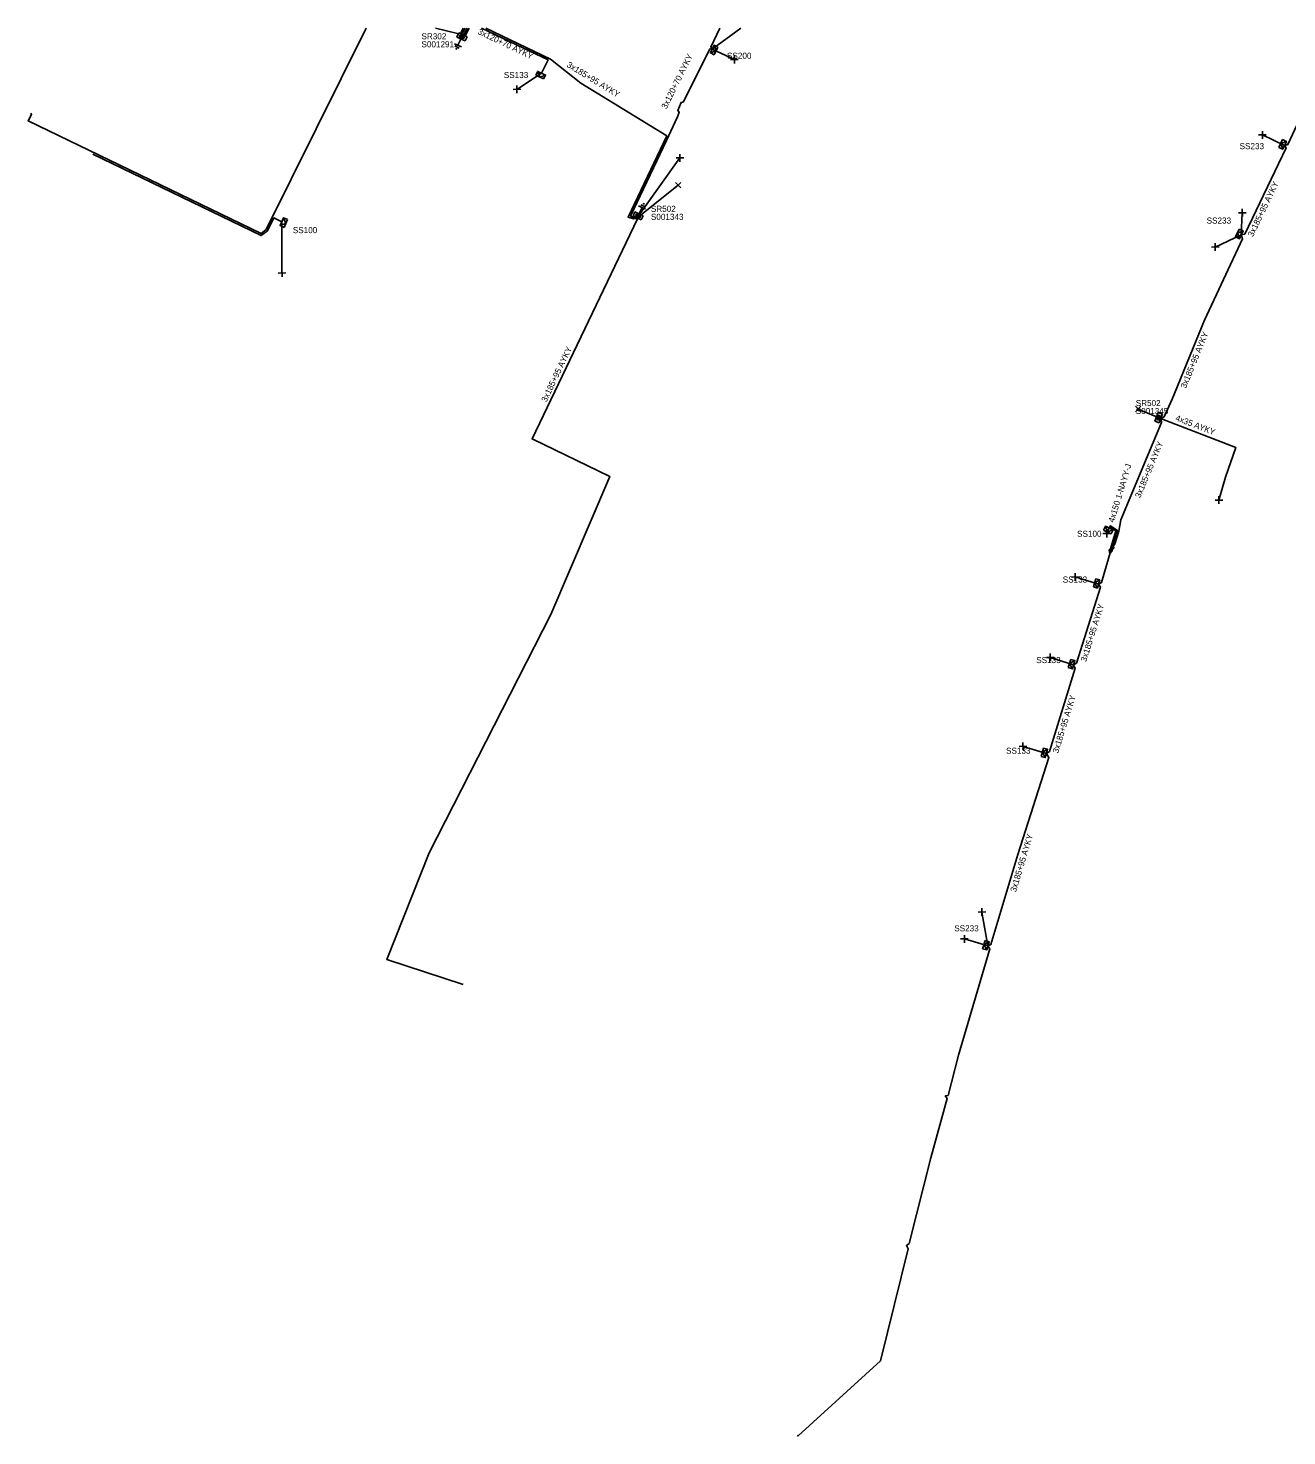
# Model space of a CAD drawing. Extents: x -762284 to -761419, y -1155250 to -1154991.
# Drawn here: x -762284.5 to -762078.9, y -1155230 to -1155000 of the extents above; entities that cross this region are included whole.
import ezdxf

# ---------------------------------------------------------------- set-up
doc = ezdxf.new("R2010")
doc.units = 0
for name, color, linetype in [('Vrstva 15', 7, 'Continuous'), ('Vrstva 19', 7, 'Continuous'), ('Vrstva 28', 7, 'Continuous'), ('Vrstva 29', 7, 'Continuous'), ('Vrstva 30', 7, 'Continuous'), ('Vrstva 31', 7, 'Continuous'), ('Vrstva 33', 7, 'Continuous'), ('Vrstva 34', 7, 'Continuous'), ('Vrstva 5', 7, 'Continuous'), ('Vrstva 59', 7, 'Continuous'), ('Vrstva 6', 7, 'Continuous')]:
    doc.layers.add(name, color=color, linetype=linetype)

msp = doc.modelspace()

# ---------------------------------------------------------------- linework, layer by layer
at = {"layer": 'Vrstva 15'}
for points in [[(-762213.688, -1155003.069), (-762214.821, -1155002.541)], [(-762214.038, -1155003.248), (-762214.751, -1155002.915)], [(-762214.519, -1155003.371), (-762214.635, -1155003.317)], [(-762214.398, -1155003.428), (-762214.519, -1155003.371)], [(-762213.726, -1155001.672), (-762214.254, -1155002.805)], [(-762184.412, -1155028.842), (-762183.698, -1155029.175)], [(-762184.052, -1155028.663), (-762183.931, -1155028.719)], [(-762183.931, -1155028.719), (-762183.815, -1155028.773)], [(-762184.762, -1155029.021), (-762183.629, -1155029.55)], [(-762184.724, -1155030.418), (-762184.195, -1155029.286)]]:
    msp.add_lwpolyline(points, dxfattribs=at)
at = {"layer": 'Vrstva 19'}
for points in [[(-762107.407, -1155085.384), (-762107.521, -1155084.836), (-762107.89, -1155085.255), (-762107.78, -1155085.802), (-762107.407, -1155085.384)], [(-762107.551, -1155084.963), (-762107.83, -1155085.271), (-762107.745, -1155085.669), (-762107.468, -1155085.368), (-762107.551, -1155084.963)], [(-762107.584, -1155085.084), (-762107.769, -1155085.287), (-762107.712, -1155085.563), (-762107.529, -1155085.352), (-762107.584, -1155085.084)], [(-762107.615, -1155085.202), (-762107.708, -1155085.304), (-762107.681, -1155085.446), (-762107.59, -1155085.335), (-762107.615, -1155085.202)], [(-762107.15, -1155084.903), (-762107.245, -1155084.352), (-762107.629, -1155084.757), (-762107.538, -1155085.308), (-762107.15, -1155084.903)], [(-762107.279, -1155084.477), (-762107.568, -1155084.776), (-762107.497, -1155085.176), (-762107.211, -1155084.885), (-762107.279, -1155084.477)], [(-762107.316, -1155084.597), (-762107.508, -1155084.794), (-762107.461, -1155085.072), (-762107.271, -1155084.867), (-762107.316, -1155084.597)], [(-762107.352, -1155084.714), (-762107.448, -1155084.812), (-762107.426, -1155084.955), (-762107.331, -1155084.848), (-762107.352, -1155084.714)]]:
    msp.add_lwpolyline(points, dxfattribs=at)
at = {"layer": 'Vrstva 28'}
for points in [[(-762214.136, -1155000.771), (-762214.453, -1155001.45)], [(-762212.777, -1155001.404), (-762214.136, -1155000.771)], [(-762213.876, -1155001.094), (-762214.036, -1155001.436)], [(-762213.853, -1155001.157), (-762213.973, -1155001.413)], [(-762213.831, -1155001.219), (-762213.91, -1155001.391)], [(-762213.202, -1155001.408), (-762213.876, -1155001.094)], [(-762213.265, -1155001.431), (-762213.853, -1155001.157)], [(-762213.808, -1155001.282), (-762213.848, -1155001.368)], [(-762213.327, -1155001.454), (-762213.831, -1155001.219)], [(-762213.39, -1155001.477), (-762213.808, -1155001.282)], [(-762214.453, -1155001.45), (-762213.094, -1155002.084)], [(-762214.036, -1155001.436), (-762213.362, -1155001.751)], [(-762213.973, -1155001.413), (-762213.384, -1155001.688)], [(-762213.91, -1155001.391), (-762213.407, -1155001.625)], [(-762213.848, -1155001.368), (-762213.43, -1155001.562)], [(-762213.79, -1155001.342), (-762213.448, -1155001.502)], [(-762213.43, -1155001.562), (-762213.39, -1155001.477)], [(-762213.407, -1155001.625), (-762213.327, -1155001.454)], [(-762213.384, -1155001.688), (-762213.265, -1155001.431)], [(-762213.362, -1155001.751), (-762213.202, -1155001.408)], [(-762213.094, -1155002.084), (-762212.777, -1155001.404)], [(-762185.356, -1155030.005), (-762185.673, -1155030.685)], [(-762185.673, -1155030.685), (-762184.314, -1155031.319)], [(-762183.997, -1155030.639), (-762185.356, -1155030.005)], [(-762185.088, -1155030.339), (-762185.248, -1155030.681)], [(-762185.248, -1155030.681), (-762184.574, -1155030.996)], [(-762185.065, -1155030.401), (-762185.185, -1155030.658)], [(-762185.185, -1155030.658), (-762184.596, -1155030.933)], [(-762185.043, -1155030.464), (-762185.122, -1155030.636)], [(-762185.122, -1155030.636), (-762184.619, -1155030.87)], [(-762184.414, -1155030.653), (-762185.088, -1155030.339)], [(-762184.477, -1155030.676), (-762185.065, -1155030.401)], [(-762185.02, -1155030.527), (-762185.06, -1155030.613)], [(-762185.06, -1155030.613), (-762184.642, -1155030.807)], [(-762184.539, -1155030.699), (-762185.043, -1155030.464)], [(-762184.602, -1155030.722), (-762185.02, -1155030.527)], [(-762184.66, -1155030.747), (-762185.002, -1155030.587)], [(-762184.642, -1155030.807), (-762184.602, -1155030.722)], [(-762184.619, -1155030.87), (-762184.539, -1155030.699)], [(-762184.596, -1155030.933), (-762184.477, -1155030.676)], [(-762184.574, -1155030.996), (-762184.414, -1155030.653)], [(-762184.314, -1155031.319), (-762183.997, -1155030.639)], [(-762099.902, -1155062.807), (-762100.464, -1155064.198)], [(-762099.866, -1155063.223), (-762100.145, -1155063.913)], [(-762099.84, -1155063.285), (-762100.084, -1155063.887)], [(-762099.814, -1155063.346), (-762100.022, -1155063.861)], [(-762099.788, -1155063.408), (-762099.961, -1155063.835)], [(-762099.207, -1155063.088), (-762099.902, -1155062.807)], [(-762099.516, -1155063.365), (-762099.866, -1155063.223)], [(-762099.847, -1155063.932), (-762099.639, -1155063.417)], [(-762099.577, -1155063.391), (-762099.84, -1155063.285)], [(-762099.821, -1155063.993), (-762099.577, -1155063.391)], [(-762099.639, -1155063.417), (-762099.814, -1155063.346)], [(-762099.795, -1155064.055), (-762099.516, -1155063.365)], [(-762099.7, -1155063.443), (-762099.788, -1155063.408)], [(-762099.769, -1155064.479), (-762099.207, -1155063.088)], [(-762100.464, -1155064.198), (-762099.769, -1155064.479)], [(-762100.145, -1155063.913), (-762099.795, -1155064.055)], [(-762100.084, -1155063.887), (-762099.821, -1155063.993)], [(-762100.022, -1155063.861), (-762099.847, -1155063.932)], [(-762099.961, -1155063.835), (-762099.873, -1155063.87)], [(-762099.76, -1155063.464), (-762099.901, -1155063.814)], [(-762099.873, -1155063.87), (-762099.7, -1155063.443)]]:
    msp.add_lwpolyline(points, dxfattribs=at)
at = {"layer": 'Vrstva 31'}
for points in [[(-762172.392, -1155004.353), (-762173.027, -1155004.058), (-762172.435, -1155002.789), (-762171.801, -1155003.085)], [(-762172.096, -1155003.719), (-762172.435, -1155002.789)], [(-762172.392, -1155004.353), (-762171.801, -1155003.085)], [(-762172.096, -1155003.719), (-762173.027, -1155004.058)], [(-762201.528, -1155007.692), (-762201.222, -1155007.063), (-762199.963, -1155007.676), (-762200.27, -1155008.305)], [(-762201.528, -1155007.692), (-762200.27, -1155008.305)], [(-762200.899, -1155007.999), (-762201.222, -1155007.063)], [(-762200.899, -1155007.999), (-762199.963, -1155007.676)], [(-762079.608, -1155018.217), (-762080.199, -1155019.486)], [(-762079.608, -1155018.217), (-762078.973, -1155018.513), (-762079.565, -1155019.781), (-762080.199, -1155019.486)], [(-762079.903, -1155018.851), (-762078.973, -1155018.513)], [(-762079.903, -1155018.851), (-762079.565, -1155019.781)], [(-762242.666, -1155032.547), (-762243.306, -1155032.263), (-762242.736, -1155030.984), (-762242.097, -1155031.268)], [(-762242.382, -1155031.908), (-762242.736, -1155030.984)], [(-762242.382, -1155031.908), (-762243.306, -1155032.263)], [(-762242.666, -1155032.547), (-762242.097, -1155031.268)], [(-762086.667, -1155032.837), (-762087.259, -1155034.106)], [(-762086.667, -1155032.837), (-762086.033, -1155033.133), (-762086.625, -1155034.402), (-762087.259, -1155034.106)], [(-762086.963, -1155033.472), (-762086.033, -1155033.133)], [(-762086.963, -1155033.472), (-762086.625, -1155034.402)], [(-762108.833, -1155081.997), (-762108.537, -1155081.363), (-762107.268, -1155081.955), (-762107.564, -1155082.589)], [(-762108.198, -1155082.293), (-762108.537, -1155081.363)], [(-762108.833, -1155081.997), (-762107.564, -1155082.589)], [(-762108.198, -1155082.293), (-762107.268, -1155081.955)], [(-762110.109, -1155089.941), (-762110.495, -1155091.287)], [(-762110.109, -1155089.941), (-762109.436, -1155090.134), (-762109.822, -1155091.48), (-762110.495, -1155091.287)], [(-762110.302, -1155090.614), (-762109.436, -1155090.134)], [(-762110.302, -1155090.614), (-762109.822, -1155091.48)], [(-762114.174, -1155103.123), (-762114.583, -1155104.462)], [(-762114.174, -1155103.123), (-762113.505, -1155103.328), (-762113.914, -1155104.666), (-762114.583, -1155104.462)], [(-762114.379, -1155103.792), (-762113.505, -1155103.328)], [(-762114.379, -1155103.792), (-762113.914, -1155104.666)], [(-762118.629, -1155117.621), (-762119.015, -1155118.967)], [(-762118.629, -1155117.621), (-762117.956, -1155117.814), (-762118.342, -1155119.16), (-762119.015, -1155118.967)], [(-762118.822, -1155118.294), (-762117.956, -1155117.814)], [(-762118.822, -1155118.294), (-762118.342, -1155119.16)], [(-762128.189, -1155149.051), (-762128.575, -1155150.397)], [(-762128.189, -1155149.051), (-762127.516, -1155149.244), (-762127.902, -1155150.59), (-762128.575, -1155150.397)], [(-762128.382, -1155149.724), (-762127.516, -1155149.244)], [(-762128.382, -1155149.724), (-762127.902, -1155150.59)]]:
    msp.add_lwpolyline(points, dxfattribs=at)
at = {"layer": 'Vrstva 34'}
for points in [[(-762169.735, -1155005.141), (-762168.485, -1155005.119)], [(-762169.099, -1155005.755), (-762169.121, -1155004.505)], [(-762205.255, -1155010.011), (-762204.005, -1155009.989)], [(-762204.619, -1155010.625), (-762204.641, -1155009.375)], [(-762083.505, -1155017.441), (-762082.255, -1155017.419)], [(-762082.869, -1155018.055), (-762082.891, -1155016.805)], [(-762178.645, -1155021.201), (-762177.395, -1155021.179)], [(-762178.009, -1155021.815), (-762178.031, -1155020.565)], [(-762178.752, -1155025.188), (-762177.868, -1155026.072)], [(-762178.752, -1155026.072), (-762177.868, -1155025.188)], [(-762086.795, -1155030.171), (-762085.545, -1155030.149)], [(-762086.159, -1155030.785), (-762086.181, -1155029.535)], [(-762091.215, -1155035.771), (-762089.965, -1155035.749)], [(-762090.579, -1155036.385), (-762090.601, -1155035.135)], [(-762243.625, -1155040.011), (-762242.375, -1155039.989)], [(-762242.989, -1155040.625), (-762243.011, -1155039.375)], [(-762103.622, -1155061.778), (-762102.738, -1155062.662)], [(-762103.622, -1155062.662), (-762102.738, -1155061.778)], [(-762090.615, -1155077.111), (-762089.365, -1155077.089)], [(-762089.979, -1155077.725), (-762090.001, -1155076.475)], [(-762108.955, -1155082.571), (-762107.705, -1155082.549)], [(-762108.319, -1155083.185), (-762108.341, -1155081.935)], [(-762114.085, -1155089.671), (-762112.835, -1155089.649)], [(-762113.449, -1155090.285), (-762113.471, -1155089.035)], [(-762117.519, -1155103.425), (-762117.541, -1155102.175)], [(-762118.155, -1155102.811), (-762116.905, -1155102.789)], [(-762122.605, -1155117.341), (-762121.355, -1155117.319)], [(-762121.969, -1155117.955), (-762121.991, -1155116.705)], [(-762128.689, -1155145.025), (-762128.711, -1155143.775)], [(-762129.325, -1155144.411), (-762128.075, -1155144.389)], [(-762131.529, -1155149.405), (-762131.551, -1155148.155)], [(-762132.165, -1155148.791), (-762130.915, -1155148.769)]]:
    msp.add_lwpolyline(points, dxfattribs=at)
at = {"layer": 'Vrstva 5'}
for points in [[(-762284, -1155013.88), (-762283.9, -1155014.08), (-762284.45, -1155015.14), (-762246.42, -1155033.53), (-762245.6, -1155032.92), (-762229.25, -1155000)], [(-762213.42, -1155000), (-762213.78, -1155000.74), (-762213.57, -1155000.89)], [(-762213.46, -1155000.94), (-762213.5, -1155000.84), (-762213.09, -1155000)], [(-762213.34, -1155001), (-762213.2, -1155000.93), (-762212.76, -1155000)], [(-762212.42, -1155000), (-762212.96, -1155001.11), (-762213.22, -1155001.06)], [(-762200.59, -1155007.37), (-762199.54, -1155005.19), (-762203.68, -1155003.2), (-762210.4, -1155000)], [(-762209.7, -1155000), (-762199.14, -1155005.05), (-762194.22, -1155008.99), (-762180.16, -1155017.6), (-762186.48, -1155030.9), (-762185.57, -1155031.16), (-762185.05, -1155031.12)], [(-762185.16, -1155031.06), (-762186.06, -1155030.7), (-762180.19, -1155018.34), (-762178.38, -1155014.49), (-762178.12, -1155013.75), (-762178.36, -1155013.43), (-762177.79, -1155012.13), (-762177.41, -1155012.06), (-762173.11, -1155003.38), (-762172.73, -1155003.42), (-762172.98, -1155003.11), (-762171.52, -1155000)], [(-762066.55, -1155000), (-762075.43, -1155011.9), (-762078.71, -1155018.99), (-762079.27, -1155019.15), (-762079.03, -1155019.57), (-762085.78, -1155033.68), (-762086.33, -1155033.77), (-762086.11, -1155034.42), (-762092.35, -1155047.71), (-762097.6, -1155060.59), (-762098.95, -1155063.48), (-762099.32, -1155063.71)], [(-762273.91, -1155020.57), (-762246.38, -1155033.88), (-762245.36, -1155033.11), (-762244.31, -1155031), (-762243.02, -1155031.62)], [(-762213.4, -1155156.26), (-762225.9, -1155152.16), (-762218.97, -1155134.75), (-762199.1, -1155095.81), (-762189.46, -1155073.22), (-762202.16, -1155067.11), (-762184.93, -1155031.17)], [(-762099.43, -1155063.95), (-762099.35, -1155064.43), (-762105.99, -1155080.34), (-762106.35, -1155082.16), (-762107, -1155084.23), (-762107.39, -1155084.83)], [(-762099.37, -1155063.83), (-762087.25, -1155068.49), (-762088.9, -1155073.38)], [(-762107.65, -1155085.32), (-762107.69, -1155085.07), (-762106.8, -1155082.14), (-762107.66, -1155081.54), (-762107.9, -1155081.66), (-762107.68, -1155081.28), (-762106.56, -1155082.06), (-762107.35, -1155084.62), (-762107.39, -1155084.83)], [(-762107.65, -1155085.32), (-762109.15, -1155090.57), (-762109.63, -1155090.81), (-762109.34, -1155091.32), (-762113.26, -1155103.72), (-762113.71, -1155104), (-762113.45, -1155104.54), (-762117.64, -1155118.15), (-762118.15, -1155118.49), (-762117.79, -1155119.13), (-762122.84, -1155135), (-762127.26, -1155149.71), (-762127.71, -1155149.92), (-762127.42, -1155150.42), (-762132.5, -1155167.79), (-762134.22, -1155174.36), (-762134.67, -1155174.43), (-762134.38, -1155174.87), (-762137.04, -1155184.57), (-762140.56, -1155198.53), (-762141.03, -1155198.89), (-762140.75, -1155199.4), (-762145.25, -1155217.74), (-762158.69, -1155229.97), (-762158.88, -1155229.91)]]:
    msp.add_lwpolyline(points, dxfattribs=at)
at = {"layer": 'Vrstva 59'}
for points in [[(-762214.33, -1155000.88), (-762217.95, -1155000)], [(-762172.73, -1155003.42), (-762168.08, -1155000)], [(-762172.73, -1155003.42), (-762169.11, -1155005.13)], [(-762200.59, -1155007.37), (-762204.63, -1155010)], [(-762079.27, -1155019.15), (-762082.88, -1155017.43)], [(-762184.5, -1155030.3), (-762178.02, -1155021.19)], [(-762184.23, -1155030.39), (-762178.31, -1155025.63)], [(-762086.33, -1155033.77), (-762086.17, -1155030.16)], [(-762243.02, -1155031.62), (-762243, -1155040)], [(-762086.33, -1155033.77), (-762090.59, -1155035.76)], [(-762100.3, -1155063.44), (-762103.18, -1155062.22)], [(-762088.9, -1155073.38), (-762089.99, -1155077.1)], [(-762107.9, -1155081.66), (-762108.33, -1155082.56)], [(-762109.63, -1155090.81), (-762113.46, -1155089.66)], [(-762113.71, -1155104), (-762117.53, -1155102.8)], [(-762118.15, -1155118.49), (-762121.98, -1155117.33)], [(-762127.71, -1155149.92), (-762128.7, -1155144.4)], [(-762127.71, -1155149.92), (-762131.54, -1155148.78)]]:
    msp.add_lwpolyline(points, dxfattribs=at)

# ---------------------------------------------------------------- texts
at = {"layer": 'Vrstva 29'}
for s, p in [('S001291', (-762220.22, -1155003.13)), ('S001343', (-762182.75, -1155031.32)), ('S001345', (-762103.57, -1155063.04))]:
    msp.add_text(s, height=0.9943, dxfattribs=at).set_placement(p)
at = {"layer": 'Vrstva 30'}
for s, p in [('SR302', (-762220.22, -1155001.83)), ('SR502', (-762182.75, -1155030.01)), ('SR502', (-762103.57, -1155061.74))]:
    msp.add_text(s, height=0.9943, dxfattribs=at).set_placement(p)
at = {"layer": 'Vrstva 33'}
for s, p in [('SS200', (-762170.32, -1155005)), ('SS133', (-762206.77, -1155008.15)), ('SS233', (-762086.61, -1155019.77)), ('SS233', (-762091.99, -1155031.93)), ('SS100', (-762241.23, -1155033.49)), ('SS100', (-762113.15, -1155083.1)), ('SS133', (-762115.49, -1155090.57)), ('SS133', (-762119.82, -1155103.73)), ('SS133', (-762124.75, -1155118.54)), ('SS233', (-762133.21, -1155147.55))]:
    msp.add_text(s, height=0.9943, dxfattribs=at).set_placement(p)
at = {"layer": 'Vrstva 6'}
for s, height, rotation, p in [('3x120+70 AYKY', 0.99429, 334.52522, (-762211.13, -1155000.9)), ('3x185+95 AYKY', 0.99429, 328.5162, (-762196.58, -1155006.26)), ('3x120+70 AYKY', 0.99429, 63.62016, (-762180.22, -1155013.3)), ('3x185+95 AYKY', 0.99428, 64.42265, (-762084.43, -1155034.18)), ('3x185+95 AYKY', 0.99429, 67.81995, (-762095.38, -1155058.94)), ('3x185+95 AYKY', 0.99429, 64.57134, (-762199.81, -1155061.18)), ('4x35 AYKY', 0.9943, 338.97064, (-762097.18, -1155064.07)), ('3x185+95 AYKY', 0.99429, 67.33918, (-762102.83, -1155076.82)), ('4x150 1-NAYY-J', 0.99429, 73.00173, (-762107.14, -1155080.83)), ('3x185+95 AYKY', 0.99428, 72.49301, (-762111.66, -1155103.59)), ('3x185+95 AYKY', 0.99428, 72.90644, (-762116.24, -1155118.52)), ('3x185+95 AYKY', 0.99429, 73.27896, (-762123.15, -1155141.21))]:
    msp.add_text(s, height=height, rotation=rotation, dxfattribs=at).set_placement(p)

doc.saveas('drawing.dxf')
